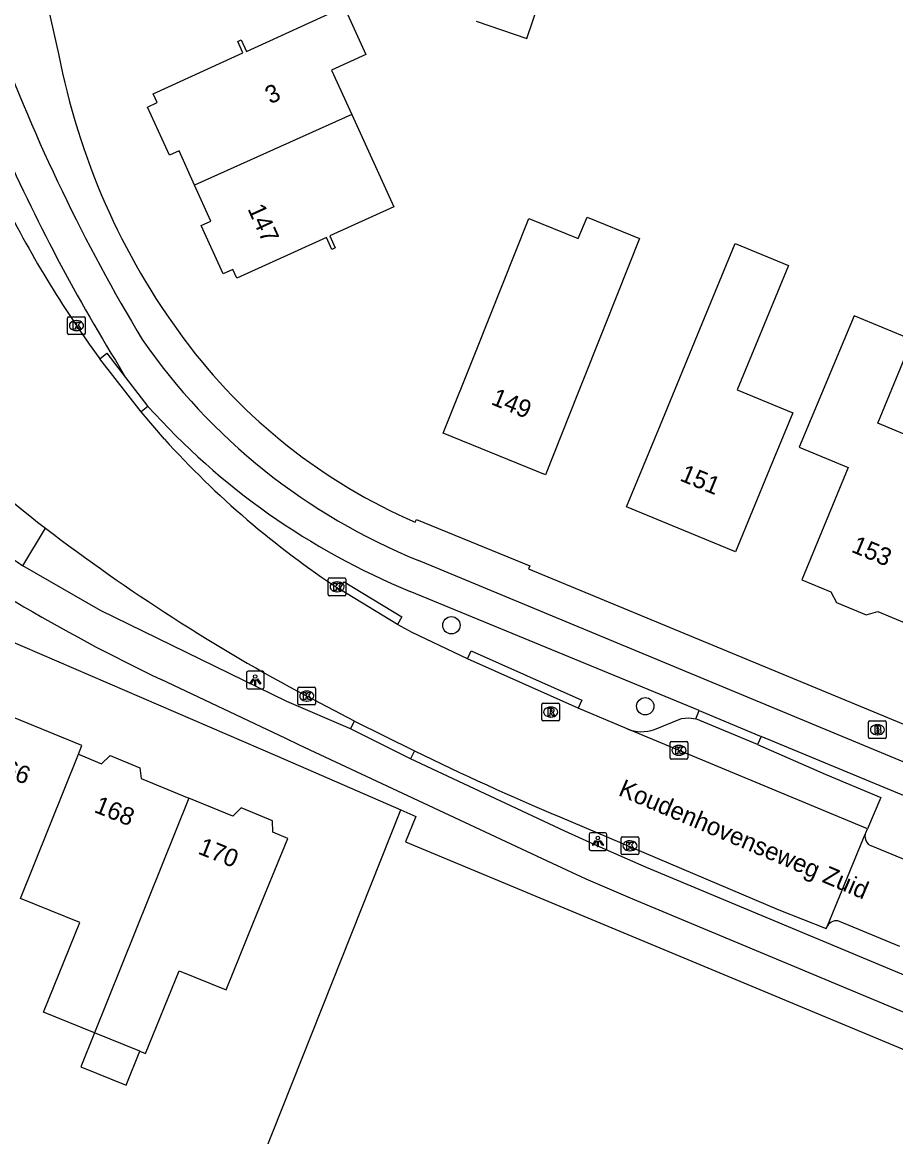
# Model space of a CAD drawing. Extents: x 162880 to 165536, y 384011 to 385179.
# Drawn here: x 163777.7 to 163826.9, y 384559.2 to 384622 of the extents above; entities that cross this region are included whole.
import ezdxf

# ---------------------------------------------------------------- set-up
doc = ezdxf.new("R2010")
doc.units = 0
for name, color, linetype in [('IMGEO_Boom', 7, 'Continuous'), ('IMGEO_Bouwland', 7, 'Continuous'), ('IMGEO_Brandkraan', 7, 'Continuous'), ('IMGEO_Fietspad_gesloten', 7, 'Continuous'), ('IMGEO_Kolk', 7, 'Continuous'), ('IMGEO_Lichtpunt', 7, 'Continuous'), ('IMGEO_Openbare_ruimte_label', 7, 'Continuous'), ('IMGEO_Pand', 7, 'Continuous'), ('IMGEO_Pand_nummerreeks', 7, 'Continuous'), ('IMGEO_Parkeervlak_open', 7, 'Continuous'), ('IMGEO_Rijbaan_lokaal_gesloten', 7, 'Continuous'), ('IMGEO_Rijbaan_lokaal_open', 7, 'Continuous'), ('IMGEO_Rioolput', 7, 'Continuous'), ('IMGEO_Verkeerseiland_open', 7, 'Continuous'), ('IMGEO_Voetpad_open', 7, 'Continuous')]:
    doc.layers.add(name, color=color, linetype=linetype)

msp = doc.modelspace()

# ---------------------------------------------------------------- linework, layer by layer
at = {"layer": 'IMGEO_Boom'}
for centre in [(163801.864, 384588.054), (163812.795, 384583.492)]:
    msp.add_circle(centre, 0.489, dxfattribs=at)
at = {"layer": 'IMGEO_Bouwland'}
msp.add_lwpolyline([(163777.851, 384524.403), (163799.02, 384577.651)], dxfattribs=at)
at = {"layer": 'IMGEO_Brandkraan'}
for p, q in [((163825.393, 384581.739), (163825.393, 384582.591)), ((163825.468, 384582.665), (163826.32, 384582.665)), ((163825.881, 384582.445), (163825.906, 384582.445)), ((163826.394, 384582.591), (163826.394, 384581.739)), ((163826.32, 384581.665), (163825.468, 384581.665)), ((163825.904, 384581.885), (163825.879, 384581.885))]:
    msp.add_line(p, q, dxfattribs=at)
for points in [[(163825.393, 384581.739), (163825.393, 384582.591)], [(163825.468, 384582.665), (163826.32, 384582.665)], [(163825.741, 384582.365), (163825.741, 384581.965), (163825.954, 384581.965)], [(163825.972, 384582.365), (163825.741, 384582.365)], [(163825.92, 384582.284), (163825.866, 384582.284), (163825.866, 384582.208)], [(163825.866, 384582.208), (163825.919, 384582.208)], [(163825.928, 384582.132), (163825.866, 384582.132), (163825.866, 384582.051)], [(163826.394, 384582.591), (163826.394, 384581.739)], [(163826.32, 384581.665), (163825.468, 384581.665)], [(163825.866, 384582.051), (163825.928, 384582.051)]]:
    msp.add_lwpolyline(points, dxfattribs=at)
for centre, radius, start, end in [((163825.47, 384582.589), 0.0765, 91.55205, 178.44795), ((163825.47, 384582.589), 0.0765, 91.55205, 178.44795), ((163825.921, 384582.246), 0.0379, 267.82845, 90.93552), ((163825.929, 384582.091), 0.0404, 269.87594, 90.50774), ((163825.976, 384582.22), 0.145, 59.4692, 91.53667), ((163826.001, 384582.267), 0.0922, 285.51372, 58.15012), ((163826.006, 384582.075), 0.105, 301.31148, 78.98903), ((163826.318, 384582.589), 0.0765, 1.55205, 88.44795), ((163826.318, 384582.589), 0.0765, 1.55205, 88.44795), ((163825.47, 384581.741), 0.0765, 181.55205, 268.44795), ((163825.47, 384581.741), 0.0765, 181.55205, 268.44795), ((163825.96, 384582.216), 0.251, 268.66757, 293.53466), ((163826.318, 384581.741), 0.0765, 271.55205, 358.44795), ((163826.318, 384581.741), 0.0765, 271.55205, 358.44795)]:
    msp.add_arc(centre, radius, start, end, dxfattribs=at)
for centre, major_axis, ratio, start_param, end_param in [((163825.88, 384582.165), (-0.387, 0.002), 0.722429, 4.712389, 7.853982), ((163825.905, 384582.165), (-0.39, 0.002), 0.717154, 1.570796, 4.712389)]:
    msp.add_ellipse(centre, major_axis=major_axis, ratio=ratio, start_param=start_param, end_param=end_param, dxfattribs=at)
at = {"layer": 'IMGEO_Fietspad_gesloten'}
for points in [[(163782.912, 384602.991), (163783.485, 384602.025)], [(163783.485, 384602.025), (163784.753, 384600.391)], [(163863.164, 384565.488), (163861.273, 384566.274), (163861.262, 384566.252), (163858.577, 384567.341), (163857.889, 384567.668), (163800.004, 384591.714)], [(163796.17, 384582.21), (163792.588, 384583.756), (163782.075, 384588.887), (163777.702, 384591.4)], [(163815.838, 384583.244), (163799.535, 384589.965)], [(163861.127, 384552.196), (163860.669, 384552.399), (163850.38, 384556.646), (163849.232, 384557.122), (163812.107, 384572.625), (163809.467, 384573.741), (163807.29, 384574.754), (163793.302, 384581.295), (163792.531, 384581.666), (163785.49, 384584.993)], [(163815.838, 384583.244), (163819.328, 384581.787)], [(163799.554, 384580.523), (163796.17, 384582.21)], [(163832.206, 384576.442), (163819.328, 384581.787)], [(163859.262, 384555.12), (163858.285, 384555.496), (163851.016, 384558.475), (163850.263, 384558.782), (163812.861, 384574.404), (163810.259, 384575.54), (163808.258, 384576.447), (163799.554, 384580.523)]]:
    msp.add_lwpolyline(points, dxfattribs=at)
for centre, radius, start, end in [((163871.458, 384656.526), 101.571, 200.29621, 211.03255), ((163871.926, 384657.523), 104.39, 203.19906, 211.49255), ((163813.064, 384624.028), 34.854, 214.74581, 247.9938), ((163814.952, 384627.515), 40.592, 221.92967, 247.67837), ((163811.599, 384641.403), 60.41, 223.70399, 235.8664), ((163831.819, 384681.633), 107.171, 239.39291, 244.38705)]:
    msp.add_arc(centre, radius, start, end, dxfattribs=at)
at = {"layer": 'IMGEO_Kolk'}
for p, q in [((163780.218, 384604.521), (163780.218, 384605.373)), ((163780.293, 384605.447), (163781.145, 384605.447)), ((163781.219, 384605.373), (163781.219, 384604.521)), ((163780.706, 384605.227), (163780.731, 384605.227)), ((163781.145, 384604.447), (163780.293, 384604.447)), ((163780.729, 384604.667), (163780.704, 384604.667)), ((163794.919, 384589.794), (163794.919, 384590.646)), ((163794.994, 384590.72), (163795.846, 384590.72)), ((163795.407, 384590.5), (163795.432, 384590.5)), ((163795.92, 384590.646), (163795.92, 384589.794)), ((163795.846, 384589.72), (163794.994, 384589.72)), ((163795.43, 384589.94), (163795.405, 384589.94)), ((163793.208, 384583.637), (163793.208, 384584.489)), ((163793.283, 384584.563), (163794.135, 384584.563)), ((163793.696, 384584.343), (163793.721, 384584.343)), ((163794.209, 384584.489), (163794.209, 384583.637)), ((163794.135, 384583.563), (163793.283, 384583.563)), ((163793.719, 384583.783), (163793.694, 384583.783)), ((163814.27, 384581.506), (163815.122, 384581.506)), ((163814.195, 384580.58), (163814.195, 384581.432)), ((163814.683, 384581.286), (163814.708, 384581.286)), ((163815.196, 384581.432), (163815.196, 384580.58)), ((163815.122, 384580.506), (163814.27, 384580.506)), ((163814.706, 384580.726), (163814.681, 384580.726)), ((163811.434, 384575.199), (163811.434, 384576.051)), ((163811.509, 384576.125), (163812.361, 384576.125)), ((163811.922, 384575.905), (163811.947, 384575.905)), ((163812.435, 384576.051), (163812.435, 384575.199)), ((163811.945, 384575.345), (163811.92, 384575.345)), ((163812.361, 384575.125), (163811.509, 384575.125))]:
    msp.add_line(p, q, dxfattribs=at)
for points in [[(163780.218, 384604.521), (163780.218, 384605.373)], [(163780.293, 384605.447), (163781.145, 384605.447)], [(163781.219, 384605.373), (163781.219, 384604.521)], [(163780.539, 384605.147), (163780.662, 384605.147), (163780.662, 384604.996), (163780.792, 384605.147), (163780.956, 384605.147), (163780.81, 384604.996), (163780.963, 384604.747), (163780.811, 384604.747), (163780.726, 384604.911), (163780.662, 384604.844), (163780.662, 384604.747), (163780.539, 384604.747), (163780.539, 384605.147)], [(163781.145, 384604.447), (163780.293, 384604.447)], [(163794.919, 384589.794), (163794.919, 384590.646)], [(163794.994, 384590.72), (163795.846, 384590.72)], [(163795.24, 384590.42), (163795.363, 384590.42), (163795.363, 384590.269), (163795.493, 384590.42), (163795.657, 384590.42), (163795.511, 384590.269), (163795.664, 384590.02), (163795.512, 384590.02), (163795.427, 384590.184), (163795.363, 384590.117), (163795.363, 384590.02), (163795.24, 384590.02), (163795.24, 384590.42)], [(163795.92, 384590.646), (163795.92, 384589.794)], [(163795.846, 384589.72), (163794.994, 384589.72)], [(163793.208, 384583.637), (163793.208, 384584.489)], [(163793.283, 384584.563), (163794.135, 384584.563)], [(163793.529, 384584.263), (163793.652, 384584.263), (163793.652, 384584.112), (163793.782, 384584.263), (163793.946, 384584.263), (163793.8, 384584.112), (163793.953, 384583.863), (163793.801, 384583.863), (163793.716, 384584.027), (163793.652, 384583.96), (163793.652, 384583.863), (163793.529, 384583.863), (163793.529, 384584.263)], [(163794.209, 384584.489), (163794.209, 384583.637)], [(163794.135, 384583.563), (163793.283, 384583.563)], [(163814.27, 384581.506), (163815.122, 384581.506)], [(163814.195, 384580.58), (163814.195, 384581.432)], [(163814.516, 384581.206), (163814.639, 384581.206), (163814.639, 384581.055), (163814.769, 384581.206), (163814.933, 384581.206), (163814.787, 384581.055), (163814.94, 384580.806), (163814.788, 384580.806), (163814.703, 384580.97), (163814.639, 384580.903), (163814.639, 384580.806), (163814.516, 384580.806), (163814.516, 384581.206)], [(163815.196, 384581.432), (163815.196, 384580.58)], [(163815.122, 384580.506), (163814.27, 384580.506)], [(163811.434, 384575.199), (163811.434, 384576.051)], [(163811.509, 384576.125), (163812.361, 384576.125)], [(163812.435, 384576.051), (163812.435, 384575.199)], [(163811.755, 384575.825), (163811.878, 384575.825), (163811.878, 384575.674), (163812.008, 384575.825), (163812.172, 384575.825), (163812.026, 384575.674), (163812.179, 384575.425), (163812.027, 384575.425), (163811.942, 384575.589), (163811.878, 384575.522), (163811.878, 384575.425), (163811.755, 384575.425), (163811.755, 384575.825)], [(163812.361, 384575.125), (163811.509, 384575.125)]]:
    msp.add_lwpolyline(points, dxfattribs=at)
for centre, start, end in [((163780.295, 384605.371), 91.55205, 178.44795), ((163780.295, 384605.371), 91.55205, 178.44795), ((163781.143, 384605.371), 1.55205, 88.44795), ((163781.143, 384605.371), 1.55205, 88.44795), ((163780.295, 384604.523), 181.55205, 268.44795), ((163780.295, 384604.523), 181.55205, 268.44795), ((163781.143, 384604.523), 271.55205, 358.44795), ((163781.143, 384604.523), 271.55205, 358.44795), ((163794.996, 384590.644), 91.55205, 178.44795), ((163794.996, 384590.644), 91.55205, 178.44795), ((163795.844, 384590.644), 1.55205, 88.44795), ((163795.844, 384590.644), 1.55205, 88.44795), ((163794.996, 384589.796), 181.55205, 268.44795), ((163794.996, 384589.796), 181.55205, 268.44795), ((163795.844, 384589.796), 271.55205, 358.44795), ((163795.844, 384589.796), 271.55205, 358.44795), ((163793.285, 384584.487), 91.55205, 178.44795), ((163793.285, 384584.487), 91.55205, 178.44795), ((163794.133, 384584.487), 1.55205, 88.44795), ((163794.133, 384584.487), 1.55205, 88.44795), ((163793.285, 384583.639), 181.55205, 268.44795), ((163793.285, 384583.639), 181.55205, 268.44795), ((163794.133, 384583.639), 271.55205, 358.44795), ((163794.133, 384583.639), 271.55205, 358.44795), ((163814.272, 384581.43), 91.55205, 178.44795), ((163814.272, 384581.43), 91.55205, 178.44795), ((163815.12, 384581.43), 1.55205, 88.44795), ((163815.12, 384581.43), 1.55205, 88.44795), ((163814.272, 384580.582), 181.55205, 268.44795), ((163814.272, 384580.582), 181.55205, 268.44795), ((163815.12, 384580.582), 271.55205, 358.44795), ((163815.12, 384580.582), 271.55205, 358.44795), ((163811.511, 384576.049), 91.55205, 178.44795), ((163811.511, 384576.049), 91.55205, 178.44795), ((163812.359, 384576.049), 1.55205, 88.44795), ((163812.359, 384576.049), 1.55205, 88.44795), ((163811.511, 384575.201), 181.55205, 268.44795), ((163811.511, 384575.201), 181.55205, 268.44795), ((163812.359, 384575.201), 271.55205, 358.44795), ((163812.359, 384575.201), 271.55205, 358.44795)]:
    msp.add_arc(centre, 0.0765, start, end, dxfattribs=at)
for centre, major_axis, ratio, start_param, end_param in [((163780.705, 384604.947), (-0.387, 0.002), 0.722429, 4.712389, 7.853982), ((163780.73, 384604.947), (-0.39, 0.002), 0.717154, 1.570796, 4.712389), ((163795.406, 384590.22), (-0.387, 0.002), 0.722429, 4.712389, 7.853982), ((163795.431, 384590.22), (-0.39, 0.002), 0.717154, 1.570796, 4.712389), ((163793.695, 384584.063), (-0.387, 0.002), 0.722429, 4.712389, 7.853982), ((163793.72, 384584.063), (-0.39, 0.002), 0.717154, 1.570796, 4.712389), ((163814.682, 384581.006), (-0.387, 0.002), 0.722429, 4.712389, 7.853982), ((163814.707, 384581.006), (-0.39, 0.002), 0.717154, 1.570796, 4.712389), ((163811.921, 384575.625), (-0.387, 0.002), 0.722429, 4.712389, 7.853982), ((163811.946, 384575.625), (-0.39, 0.002), 0.717154, 1.570796, 4.712389)]:
    msp.add_ellipse(centre, major_axis=major_axis, ratio=ratio, start_param=start_param, end_param=end_param, dxfattribs=at)
at = {"layer": 'IMGEO_Lichtpunt'}
for p, q in [((163790.302, 384585.368), (163790.302, 384584.561)), ((163790.302, 384585.368), (163790.302, 384584.561)), ((163791.204, 384585.463), (163790.396, 384585.463)), ((163791.204, 384585.463), (163790.396, 384585.463)), ((163791.298, 384584.561), (163791.298, 384585.368)), ((163791.298, 384584.561), (163791.298, 384585.368)), ((163790.396, 384584.467), (163791.204, 384584.467)), ((163790.396, 384584.467), (163791.204, 384584.467)), ((163809.627, 384576.265), (163809.627, 384575.458)), ((163809.627, 384576.265), (163809.627, 384575.458)), ((163810.529, 384576.36), (163809.721, 384576.36)), ((163810.529, 384576.36), (163809.721, 384576.36)), ((163810.623, 384575.458), (163810.623, 384576.265)), ((163810.623, 384575.458), (163810.623, 384576.265)), ((163809.721, 384575.364), (163810.529, 384575.364)), ((163809.721, 384575.364), (163810.529, 384575.364))]:
    msp.add_line(p, q, dxfattribs=at)
for points in [[(163790.676, 384585.032), (163790.715, 384585.004), (163790.527, 384584.742), (163790.489, 384584.769), (163790.676, 384585.032)], [(163790.778, 384584.984), (163790.825, 384584.984), (163790.825, 384584.662), (163790.778, 384584.662), (163790.778, 384584.984)], [(163790.888, 384585.004), (163790.926, 384585.031), (163791.113, 384584.769), (163791.074, 384584.741), (163790.888, 384585.004)], [(163810.001, 384575.929), (163810.04, 384575.901), (163809.852, 384575.639), (163809.814, 384575.666), (163810.001, 384575.929)], [(163810.103, 384575.881), (163810.15, 384575.881), (163810.15, 384575.559), (163810.103, 384575.559), (163810.103, 384575.881)], [(163810.213, 384575.901), (163810.251, 384575.928), (163810.438, 384575.666), (163810.399, 384575.638), (163810.213, 384575.901)]]:
    msp.add_lwpolyline(points, dxfattribs=at)
for centre in [(163790.801, 384585.166), (163810.126, 384576.063)]:
    msp.add_circle(centre, 0.0994, dxfattribs=at)
for centre, start, end in [((163790.396, 384585.368), 90, 180), ((163790.396, 384585.368), 90, 180), ((163791.204, 384585.368), 0, 90), ((163791.204, 384585.368), 0, 90), ((163790.396, 384584.561), 180, 270), ((163790.396, 384584.561), 180, 270), ((163791.204, 384584.561), 270, 0), ((163791.204, 384584.561), 270, 360), ((163809.721, 384576.265), 90, 180), ((163809.721, 384576.265), 90, 180), ((163810.529, 384576.265), 0, 90), ((163810.529, 384576.265), 0, 90), ((163809.721, 384575.458), 180, 270), ((163809.721, 384575.458), 180, 270), ((163810.529, 384575.458), 270, 0), ((163810.529, 384575.458), 270, 360)]:
    msp.add_arc(centre, 0.0946, start, end, dxfattribs=at)
at = {"layer": 'IMGEO_Pand'}
for points in [[(163803.256, 384622.106), (163806.126, 384621.137), (163807.155, 384624.185), (163807.439, 384625.083)], [(163787.382, 384612.862), (163786.505, 384614.792), (163785.959, 384614.544), (163784.723, 384617.267), (163785.27, 384617.516), (163785.044, 384618.015), (163785.258, 384618.112), (163790.111, 384620.317), (163789.818, 384620.965), (163790.009, 384621.051), (163790.302, 384620.404), (163795.819, 384622.911), (163797.04, 384620.226), (163795.11, 384619.349), (163796.25, 384616.84)], [(163796.25, 384616.84), (163787.382, 384612.862)], [(163796.25, 384616.84), (163798.615, 384611.638), (163795.011, 384610), (163795.318, 384609.327), (163795.127, 384609.241), (163794.82, 384609.914), (163789.976, 384607.712), (163789.762, 384607.615), (163789.539, 384608.107), (163788.993, 384607.859), (163787.757, 384610.582), (163788.304, 384610.831), (163787.382, 384612.862)], [(163809.021, 384601.177), (163807.17, 384596.532), (163801.408, 384598.883), (163803.26, 384603.528), (163806.235, 384610.988), (163809.019, 384609.848), (163809.516, 384611.061), (163812.476, 384609.849), (163810.538, 384604.985), (163809.021, 384601.177)], [(163819.008, 384603.818), (163817.976, 384601.317), (163821.119, 384600.02), (163819.812, 384596.853), (163817.887, 384592.188), (163811.745, 384594.722), (163813.656, 384599.355), (163816.009, 384605.056), (163817.874, 384609.574), (163820.872, 384608.337), (163819.008, 384603.818)], [(163829.456, 384592.77), (163831.309, 384597.197), (163825.912, 384599.455), (163827.855, 384604.15), (163824.577, 384605.491), (163823.415, 384602.716), (163821.484, 384598.103), (163824.242, 384596.94), (163821.638, 384590.621), (163823.27, 384589.934), (163823.592, 384589.337), (163825.258, 384588.638), (163825.909, 384588.838), (163827.525, 384588.157), (163829.456, 384592.77)], [(163780.829, 384580.783), (163781.031, 384581.278), (163775.274, 384583.627), (163770.325, 384571.498)], [(163777.564, 384572.653), (163780.829, 384580.783)], [(163780.829, 384580.783), (163782.137, 384580.249), (163782.616, 384580.707), (163784.297, 384580.021), (163784.37, 384579.409), (163787.052, 384578.314)], [(163787.052, 384578.314), (163781.733, 384565.077)], [(163784.288, 384564.042), (163784.618, 384563.908), (163786.511, 384568.579), (163789.154, 384567.508), (163790.749, 384571.416), (163792.638, 384576.045), (163791.796, 384576.389), (163791.766, 384577.039), (163790.001, 384577.759), (163789.535, 384577.301), (163787.052, 384578.314)], [(163781.733, 384565.077), (163778.857, 384566.242), (163780.906, 384571.299), (163777.564, 384572.653)], [(163781.733, 384565.077), (163780.959, 384563.166), (163783.514, 384562.13), (163784.288, 384564.042)], [(163784.288, 384564.042), (163781.733, 384565.077)]]:
    msp.add_lwpolyline(points, dxfattribs=at)
at = {"layer": 'IMGEO_Parkeervlak_open'}
for points in [[(163813.317, 384582.178), (163814.851, 384582.8), (163815.261, 384582.834), (163815.646, 384582.783)], [(163819.136, 384581.326), (163822.94, 384579.667), (163826.081, 384578.351), (163825.33, 384576.589)]]:
    msp.add_lwpolyline(points, dxfattribs=at)
msp.add_arc((163812.593, 384584.24), 2.185, 248.33003, 289.35001, dxfattribs=at)
at = {"layer": 'IMGEO_Rijbaan_lokaal_gesloten'}
for points in [[(163784.359, 384600.085), (163782.034, 384603.08)], [(163785.676, 384598.55), (163784.359, 384600.085)], [(163798.817, 384588.102), (163795.556, 384590.084)], [(163802.773, 384586.162), (163799.658, 384587.642), (163798.817, 384588.102)], [(163809.013, 384583.374), (163802.773, 384586.162)], [(163796.393, 384582.657), (163793.705, 384584.064)], [(163811.786, 384582.209), (163809.013, 384583.374)], [(163796.393, 384582.657), (163799.777, 384580.97)], [(163825.33, 384576.589), (163811.786, 384582.209)], [(163807.983, 384577.25), (163820.328, 384572.015), (163823.01, 384570.956), (163823.058, 384571.066), (163823.069, 384571.09), (163823.081, 384571.114)], [(163825.204, 384576.274), (163825.231, 384576.358), (163825.33, 384576.589)], [(163823.081, 384571.114), (163825.204, 384576.274)]]:
    msp.add_lwpolyline(points, dxfattribs=at)
for centre, radius, start, end in [((163831.461, 384639.294), 61.274, 206.15462, 216.22948), ((163820.193, 384646.793), 67.355, 216.75512, 232.27363), ((163824.128, 384633.426), 51.913, 222.20825, 236.60636), ((163844.661, 384679.623), 108.296, 232.66265, 241.93142), ((163875.877, 384737.93), 174.436, 244.13407, 247.0938)]:
    msp.add_arc(centre, radius, start, end, dxfattribs=at)
at = {"layer": 'IMGEO_Rijbaan_lokaal_open'}
for points in [[(163825.204, 384576.274), (163825.19, 384576.139)], [(163825.512, 384575.636), (163828.976, 384574.206)], [(163827.165, 384569.946), (163823.757, 384571.36)]]:
    msp.add_lwpolyline(points, dxfattribs=at)
for centre, radius, start, end in [((163825.752, 384576.145), 0.563, 180.56255, 244.68887), ((163823.556, 384570.861), 0.538, 68.06027, 151.93316)]:
    msp.add_arc(centre, radius, start, end, dxfattribs=at)
at = {"layer": 'IMGEO_Rioolput'}
for p, q in [((163806.967, 384582.737), (163806.967, 384583.589)), ((163807.042, 384583.663), (163807.894, 384583.663)), ((163807.455, 384583.443), (163807.48, 384583.443)), ((163807.968, 384583.589), (163807.968, 384582.737)), ((163807.478, 384582.883), (163807.453, 384582.883)), ((163807.894, 384582.663), (163807.042, 384582.663))]:
    msp.add_line(p, q, dxfattribs=at)
for points in [[(163806.967, 384582.737), (163806.967, 384583.589)], [(163807.042, 384583.663), (163807.894, 384583.663)], [(163807.968, 384583.589), (163807.968, 384582.737)], [(163807.556, 384583.361), (163807.304, 384583.363), (163807.304, 384582.963)], [(163807.304, 384582.963), (163807.428, 384582.963), (163807.428, 384583.125), (163807.439, 384583.125)], [(163807.482, 384583.282), (163807.428, 384583.282), (163807.428, 384583.201)], [(163807.428, 384583.201), (163807.48, 384583.201)], [(163807.486, 384583.096), (163807.557, 384582.963), (163807.697, 384582.963), (163807.632, 384583.089)], [(163807.894, 384582.663), (163807.042, 384582.663)]]:
    msp.add_lwpolyline(points, dxfattribs=at)
for centre, radius, start, end in [((163807.044, 384583.587), 0.0765, 91.55205, 178.44795), ((163807.044, 384583.587), 0.0765, 91.55205, 178.44795), ((163807.892, 384583.587), 0.0765, 1.55205, 88.44795), ((163807.892, 384583.587), 0.0765, 1.55205, 88.44795), ((163807.438, 384583.072), 0.0533, 26.02933, 88.69889), ((163807.464, 384583.39), 0.19, 274.7715, 282.96867), ((163807.488, 384583.186), 0.0964, 77.00612, 93.18647), ((163807.502, 384583.243), 0.0378, 276.66336, 79.67722), ((163807.555, 384583.251), 0.109, 350.36119, 89.41601), ((163807.553, 384583.251), 0.112, 277.58423, 350.98172), ((163807.537, 384583.036), 0.108, 29.51342, 73.79051), ((163807.044, 384582.739), 0.0765, 181.55205, 268.44795), ((163807.044, 384582.739), 0.0765, 181.55205, 268.44795), ((163807.892, 384582.739), 0.0765, 271.55205, 358.44795), ((163807.892, 384582.739), 0.0765, 271.55205, 358.44795)]:
    msp.add_arc(centre, radius, start, end, dxfattribs=at)
for centre, major_axis, ratio, start_param, end_param in [((163807.454, 384583.163), (-0.387, 0.002), 0.722429, 4.712389, 7.853982), ((163807.479, 384583.163), (-0.39, 0.002), 0.717154, 1.570796, 4.712389)]:
    msp.add_ellipse(centre, major_axis=major_axis, ratio=ratio, start_param=start_param, end_param=end_param, dxfattribs=at)
at = {"layer": 'IMGEO_Verkeerseiland_open'}
msp.add_lwpolyline([(163777.702, 384591.4), (163778.979, 384593.519)], dxfattribs=at)
at = {"layer": 'IMGEO_Voetpad_open'}
for points in [[(163779.139, 384622.771), (163779.71, 384620.265)], [(163782.034, 384603.08), (163782.428, 384603.386), (163783.485, 384602.025)], [(163784.753, 384600.391), (163784.359, 384600.085)], [(163799.826, 384593.865), (163799.9, 384594.018), (163806.282, 384591.401), (163806.205, 384591.228), (163859.512, 384569.182), (163870.006, 384564.899)], [(163795.556, 384590.084), (163795.815, 384590.511), (163799.076, 384588.529), (163798.817, 384588.102)], [(163773.826, 384588.522), (163792.055, 384580.685), (163799.02, 384577.651)], [(163802.773, 384586.162), (163802.976, 384586.618), (163809.216, 384583.83), (163809.013, 384583.374)], [(163815.646, 384582.783), (163815.838, 384583.244)], [(163819.136, 384581.326), (163815.646, 384582.783)], [(163796.17, 384582.21), (163796.393, 384582.657)], [(163819.328, 384581.787), (163819.136, 384581.326)], [(163799.777, 384580.97), (163799.554, 384580.523)], [(163799.02, 384577.651), (163799.868, 384577.282), (163799.271, 384575.856), (163855.748, 384552.326), (163856.415, 384552.055)]]:
    msp.add_lwpolyline(points, dxfattribs=at)
for centre, radius, start, end in [((163818.45, 384627.717), 39.45, 190.88877, 216.59133), ((163812.523, 384623.304), 32.06, 216.57325, 246.67042)]:
    msp.add_arc(centre, radius, start, end, dxfattribs=at)

# ---------------------------------------------------------------- texts
at = {"layer": 'IMGEO_Openbare_ruimte_label'}
msp.add_text('Koudenhovenseweg Zuid', height=1, rotation=336.97451, dxfattribs=at).set_placement((163811.226, 384578.488))
at = {"layer": 'IMGEO_Pand_nummerreeks'}
for s, rotation, p in [('3', 24.43741, (163791.645, 384617.411)), ('147', 294.41383, (163790.352, 384611.531)), ('149', 337.80365, (163804.049, 384600.528)), ('151', 337.58016, (163814.692, 384596.232)), ('153', 337.28828, (163824.366, 384592.21)), ('166', 338.19896, (163775.791, 384579.887)), ('168', 338.19891, (163781.659, 384577.541)), ('170', 338.19896, (163787.52, 384575.196))]:
    msp.add_text(s, height=1, rotation=rotation, dxfattribs=at).set_placement(p)

doc.saveas('drawing.dxf')
